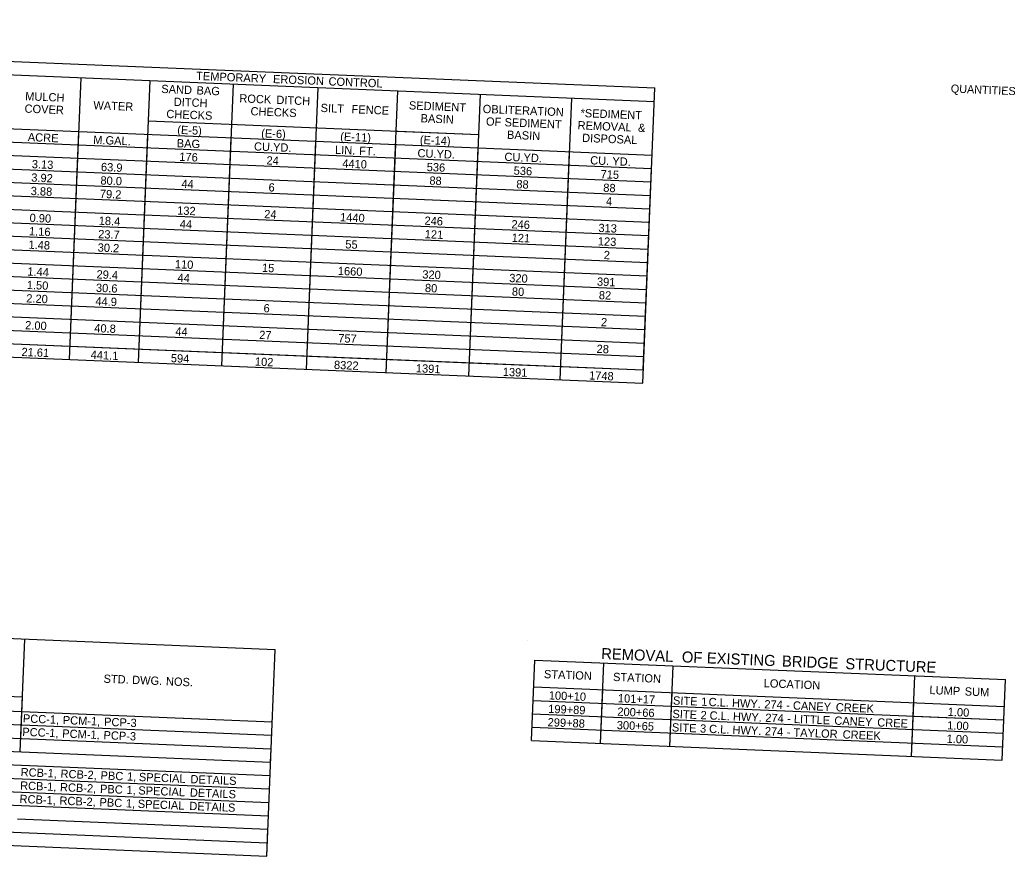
# Model space of a CAD drawing. Extents: x 1164179 to 1171425, y 1655958 to 1657208.
# Drawn here: x 1166854 to 1167576, y 1656540 to 1657146 of the extents above; entities that cross this region are included whole.
import ezdxf

# ---------------------------------------------------------------- set-up
doc = ezdxf.new("R2010")
doc.units = 0
doc.layers.add('Default', color=7, linetype='Continuous')
doc.layers.add('R_Grid', color=7, linetype='Continuous')

msp = doc.modelspace()

# ---------------------------------------------------------------- linework, layer by layer
at = {"layer": 'Default'}
for p, q in [((1166119.48, 1657146.43), (1167314.3, 1657097.01)), ((1166520.92, 1657120.07), (1167313.89, 1657087.27)), ((1166889.46, 1656899.9), (1166897.92, 1657104.47)), ((1166939.63, 1656897.82), (1166948.09, 1657102.4)), ((1167000.03, 1656895.32), (1167008.49, 1657099.9)), ((1167061.4, 1656892.79), (1167069.86, 1657097.36)), ((1167305.43, 1656882.69), (1167314.3, 1657097.01)), ((1167119.36, 1656890.39), (1167127.83, 1657094.96)), ((1167179.28, 1656887.91), (1167187.74, 1657092.48)), ((1167245.52, 1656885.17), (1167253.98, 1657089.74)), ((1166117.06, 1657087.98), (1167311.88, 1657038.56)), ((1166116.66, 1657078.24), (1167311.47, 1657028.82)), ((1166519.31, 1657081.1), (1167186.13, 1657053.52)), ((1166116.26, 1657068.5), (1167311.07, 1657019.07)), ((1166946.88, 1657073.17), (1167186.53, 1657063.26)), ((1166889.46, 1656899.9), (1166896.31, 1657065.51)), ((1166939.63, 1656897.82), (1166946.48, 1657063.43)), ((1167000.03, 1656895.32), (1167006.88, 1657060.93)), ((1167126.62, 1657065.74), (1167186.53, 1657063.26)), ((1166115.85, 1657058.76), (1167310.67, 1657009.33)), ((1167061.4, 1656892.79), (1167068.25, 1657058.39)), ((1167119.36, 1656890.39), (1167126.21, 1657056)), ((1167179.28, 1656887.91), (1167186.13, 1657053.52)), ((1167186.13, 1657053.52), (1167312.28, 1657048.3)), ((1166115.45, 1657049.02), (1167310.27, 1656999.59)), ((1167245.52, 1656885.17), (1167252.37, 1657050.78)), ((1166115.05, 1657039.28), (1167309.86, 1656989.85)), ((1167305.83, 1656892.43), (1167311.88, 1657038.56)), ((1166114.64, 1657029.53), (1167309.46, 1656980.11)), ((1166114.24, 1657019.79), (1167309.06, 1656970.37)), ((1166113.84, 1657010.05), (1167308.65, 1656960.62)), ((1166113.44, 1657000.31), (1167308.25, 1656950.88)), ((1166113.03, 1656990.57), (1167307.85, 1656941.14)), ((1166112.63, 1656980.83), (1167307.44, 1656931.4)), ((1166112.23, 1656971.08), (1167307.04, 1656921.66)), ((1166111.82, 1656961.34), (1167306.64, 1656911.92)), ((1166111.42, 1656951.6), (1167306.24, 1656902.17)), ((1166111.02, 1656941.86), (1167179.68, 1656897.65)), ((1166111.02, 1656941.86), (1167305.83, 1656892.43)), ((1166110.61, 1656932.12), (1167305.43, 1656882.69)), ((1167179.68, 1656897.65), (1167245.92, 1656894.91)), ((1167245.92, 1656894.91), (1167305.83, 1656892.43)), ((1166102.18, 1656728.34), (1167038.85, 1656689.59)), ((1166853.78, 1656615.27), (1166857.16, 1656697.1)), ((1167221.85, 1656695.68), (1167221.85, 1656695.68)), ((1167032.64, 1656539.57), (1167038.85, 1656689.59)), ((1167224.72, 1656623.35), (1167227.13, 1656681.8)), ((1167224.72, 1656623.35), (1167227.13, 1656681.8)), ((1167227.13, 1656681.8), (1167568.58, 1656667.67)), ((1167274.89, 1656621.27), (1167277.3, 1656679.72)), ((1167325.06, 1656619.2), (1167327.47, 1656677.65)), ((1166100.01, 1656675.73), (1167036.67, 1656636.98)), ((1166368.35, 1656675.36), (1166855.43, 1656655.21)), ((1167500.41, 1656611.94), (1167502.82, 1656670.39)), ((1166099.6, 1656665.99), (1167036.27, 1656627.24)), ((1167566.16, 1656609.22), (1167568.58, 1656667.67)), ((1167566.16, 1656609.22), (1167568.58, 1656667.67)), ((1166099.2, 1656656.25), (1167035.86, 1656617.5)), ((1166099.2, 1656656.25), (1167035.86, 1656617.5)), ((1167226.33, 1656662.32), (1167567.77, 1656648.19)), ((1167274.89, 1656621.27), (1167276.5, 1656660.24)), ((1167325.06, 1656619.2), (1167326.67, 1656658.16)), ((1166854.18, 1656625.02), (1166855.43, 1656655.21)), ((1167225.92, 1656652.57), (1167567.37, 1656638.45)), ((1167500.41, 1656611.94), (1167502.02, 1656650.91)), ((1166098.8, 1656646.51), (1167035.46, 1656607.76)), ((1166854.99, 1656644.5), (1167036.67, 1656636.98)), ((1167225.52, 1656642.83), (1167566.97, 1656628.71)), ((1166098.4, 1656636.76), (1167035.06, 1656598.02)), ((1167501.61, 1656641.17), (1167567.37, 1656638.45)), ((1166097.99, 1656627.02), (1167034.65, 1656588.27)), ((1167225.12, 1656633.09), (1167566.56, 1656618.97)), ((1167224.72, 1656623.35), (1167566.16, 1656609.22)), ((1166097.59, 1656617.28), (1167034.25, 1656578.53)), ((1167035.46, 1656607.76), (1167035.86, 1656617.5)), ((1166097.19, 1656607.54), (1167033.85, 1656568.79)), ((1166096.38, 1656588.06), (1167033.04, 1656549.31)), ((1166095.98, 1656578.31), (1167032.64, 1656539.57)), ((1166851.76, 1656566.57), (1167033.45, 1656559.05)), ((1167032.64, 1656539.57), (1167033.45, 1656559.05))]:
    msp.add_line(p, q, dxfattribs=at)

# ---------------------------------------------------------------- texts
for s, height, p in [('TEMPORARY', 6, (1166981.31, 1657102.9)), (' EROSION', 6, (1167034.85, 1657100.69)), (' CONTROL', 6, (1167075.14, 1657099.02)), ('SAND', 6, (1166956.06, 1657093.44)), (' BAG', 6, (1166979.38, 1657092.47)), ('MULCH', 6, (1166857.29, 1657088.14)), ('DITCH', 6, (1166965.09, 1657084.05)), ('ROCK', 6, (1167012.67, 1657086.59)), (' DITCH', 6, (1167037.32, 1657085.57)), ('COVER', 6, (1166856.85, 1657079.15)), ('WATER', 6, (1166906.74, 1657081.59)), ('CHECKS', 6, (1167020.78, 1657077.25)), ('SILT', 6, (1167071.65, 1657079.65)), ('  FENCE', 6, (1167089.63, 1657078.9)), ('SEDIMENT', 6, (1167135.68, 1657081.5)), ('OBLITERATION', 6, (1167189.23, 1657078.91)), ('*SEDIMENT', 6, (1167260.19, 1657075.98)), ('CHECKS', 6, (1166959.71, 1657075.27)), ('BASIN', 6, (1167144.17, 1657072.14)), ('OF', 6, (1167191.59, 1657069.81)), (' SEDIMENT', 6, (1167202.83, 1657069.34)), ('(E-5)', 6, (1166967.64, 1657063.76)), ('(E-6)', 6, (1167028.53, 1657061.24)), ('REMOVAL', 6, (1167258.07, 1657067.06)), (' &', 6, (1167299.71, 1657065.33)), ('ACRE', 6, (1166859.21, 1657058.48)), ('M.GAL.', 6, (1166906.67, 1657056.52)), ('(E-11)', 6, (1167085.87, 1657058.87)), ('(E-14)', 6, (1167143.64, 1657056.48)), ('BASIN', 6, (1167206.86, 1657060.17)), ('DISPOSAL', 6, (1167261.35, 1657057.91)), ('BAG', 6, (1166967.27, 1657054.01)), ('CU.YD.', 6, (1167023.31, 1657051.7)), ('LIN.', 6, (1167082.1, 1657049.26)), (' FT.', 6, (1167097.35, 1657048.63)), ('CU.YD.', 6, (1167141.91, 1657046.79)), ('176', 6, (1166969.13, 1657044.18)), ('24', 6, (1167032.36, 1657041.56)), ('CU.YD.', 6, (1167204.99, 1657044.18)), ('CU.', 6, (1167267.19, 1657041.61)), (' YD.', 6, (1167281.04, 1657041.03)), ('3.13', 6, (1166862.11, 1657038.85)), ('63.9', 6, (1166912.27, 1657036.77)), ('4410', 6, (1167087.37, 1657039.29)), ('536', 6, (1167148.62, 1657036.75)), ('536', 6, (1167211.7, 1657034.14)), ('3.92', 6, (1166861.74, 1657029.1)), ('80.0', 6, (1166911.89, 1657027.03)), ('88', 6, (1167150.54, 1657026.92)), ('715', 6, (1167274.75, 1657031.54)), ('3.88', 6, (1166861.3, 1657019.36)), ('44', 6, (1166970.66, 1657024.6)), ('6', 6, (1167033.86, 1657021.98)), ('88', 6, (1167213.62, 1657024.31)), ('88', 6, (1167276.69, 1657021.7)), ('79.2', 6, (1166911.51, 1657017.29)), ('4', 6, (1167278.64, 1657011.86)), ('132', 6, (1166967.55, 1657005.21)), ('0.90', 6, (1166860.51, 1656999.88)), ('18.4', 6, (1166910.68, 1656997.8)), ('24', 6, (1167030.74, 1657002.6)), ('1440', 6, (1167085.75, 1657000.32)), ('246', 6, (1167147.01, 1656997.79)), ('1.16', 6, (1166860.09, 1656990.14)), ('44', 6, (1166969.46, 1656995.37)), ('246', 6, (1167210.08, 1656995.18)), ('313', 6, (1167273.16, 1656992.57)), ('23.7', 6, (1166910.26, 1656988.06)), ('121', 6, (1167147.18, 1656988.02)), ('121', 6, (1167210.26, 1656985.41)), ('123', 6, (1167272.76, 1656982.83)), ('1.48', 6, (1166859.69, 1656980.4)), ('30.2', 6, (1166909.89, 1656978.32)), ('55', 6, (1167089.57, 1656980.65)), ('2', 6, (1167277.04, 1656972.89)), ('1.44', 6, (1166858.9, 1656960.91)), ('110', 6, (1166965.92, 1656966.24)), ('15', 6, (1167029.1, 1656963.63)), ('1660', 6, (1167084.14, 1656961.35)), ('29.4', 6, (1166909.07, 1656958.84)), ('44', 6, (1166967.84, 1656956.41)), ('320', 6, (1167145.41, 1656958.82)), ('320', 6, (1167208.48, 1656956.21)), ('391', 6, (1167272.13, 1656953.58)), ('1.50', 6, (1166858.49, 1656951.17)), ('30.6', 6, (1166908.65, 1656949.1)), ('80', 6, (1167147.33, 1656948.98)), ('80', 6, (1167210.41, 1656946.37)), ('2.20', 6, (1166858.09, 1656941.43)), ('44.9', 6, (1166908.24, 1656939.36)), ('82', 6, (1167273.51, 1656943.76)), ('6', 6, (1167030.24, 1656934.31)), ('2', 6, (1167275.03, 1656924.18)), ('2.00', 6, (1166857.29, 1656921.95)), ('40.8', 6, (1166907.44, 1656919.87)), ('44', 6, (1166966.23, 1656917.44)), ('27', 6, (1167027.1, 1656914.92)), ('757', 6, (1167084.44, 1656912.55)), ('21.61', 6, (1166854.63, 1656902.54)), ('28', 6, (1167271.86, 1656904.8)), ('441.1', 6, (1166904.8, 1656900.46)), ('594', 6, (1166962.99, 1656898.06)), ('102', 6, (1167023.99, 1656895.53)), ('8322', 6, (1167081.33, 1656893.16)), ('1391', 6, (1167140.74, 1656890.7)), ('1391', 6, (1167203.81, 1656888.1)), ('1748', 6, (1167266.4, 1656885.51)), ('REMOVAL', 8, (1167275.19, 1656682.64)), (' OF', 8, (1167330.7, 1656680.34)), (' EXISTING', 8, (1167348.79, 1656679.59)), (' BRIDGE', 8, (1167403.35, 1656677.34)), (' STRUCTURE', 8, (1167449.34, 1656675.43)), ('STD.', 6, (1166914.15, 1656665.4)), (' DWG.', 6, (1166932.66, 1656664.63)), ('STATION', 6, (1167233.65, 1656668.77)), ('STATION', 6, (1167283.82, 1656666.69)), (' NOS.', 6, (1166957.2, 1656663.61)), ('LOCATION', 6, (1167393.09, 1656662.17)), ('LUMP', 6, (1167513.33, 1656657.2)), ('100+10', 6, (1167237.18, 1656653.31)), ('101+17', 6, (1167287.33, 1656651.23)), (' SUM', 6, (1167536.68, 1656656.23)), ('199+89', 6, (1167236.76, 1656643.57)), ('SITE', 6, (1167327.29, 1656649.58)), (' 1', 6, (1167345.46, 1656648.83)), (' C.L.', 6, (1167350.9, 1656648.6)), (' HWY.', 6, (1167367.85, 1656647.9)), (' 274', 6, (1167391.32, 1656646.93)), (' -', 6, (1167407.2, 1656646.28)), (' CANEY', 6, (1167412.06, 1656646.07)), (' CREEK', 6, (1167443.18, 1656644.79)), ('PCC-1,', 6, (1166855.64, 1656636.59)), (' PCM-1,', 6, (1166882.35, 1656635.48)), ('200+66', 6, (1167286.93, 1656641.49)), ('SITE', 6, (1167326.88, 1656639.84)), (' 2', 6, (1167345.06, 1656639.09)), (' C.L.', 6, (1167351.6, 1656638.82)), (' HWY.', 6, (1167368.55, 1656638.12)), (' 274', 6, (1167392.01, 1656637.15)), (' LITTLE', 6, (1167412.75, 1656636.29)), ('1.00', 6, (1167526.6, 1656641.34)), (' PCP-3', 6, (1166912.31, 1656634.25)), ('299+88', 6, (1167236.35, 1656633.83)), ('300+65', 6, (1167286.5, 1656631.75)), ('SITE', 6, (1167326.48, 1656630.1)), (' 3', 6, (1167344.65, 1656629.35)), (' C.L.', 6, (1167351.26, 1656629.07)), (' HWY.', 6, (1167368.21, 1656628.37)), (' -', 6, (1167407.9, 1656636.49)), (' CANEY', 6, (1167442.09, 1656635.07)), (' CREE', 6, (1167473.22, 1656633.79)), ('1.00', 6, (1167526.19, 1656631.59)), ('PCC-1,', 6, (1166855.23, 1656626.85)), (' PCM-1,', 6, (1166881.94, 1656625.74)), (' PCP-3', 6, (1166911.91, 1656624.5)), (' 274', 6, (1167391.67, 1656627.4)), (' -', 6, (1167407.56, 1656626.74)), (' TAYLOR', 6, (1167412.41, 1656626.54)), (' CREEK', 6, (1167448.14, 1656625.07)), ('1.00', 6, (1167525.79, 1656621.85)), ('RCB-1,', 6, (1166854.02, 1656597.62)), (' RCB-2,', 6, (1166880.74, 1656596.52)), (' PBC', 6, (1166909.77, 1656595.32)), (' 1,', 6, (1166928.99, 1656594.52)), (' SPECIAL', 6, (1166937.55, 1656594.17)), (' DETAILS', 6, (1166974.97, 1656592.62)), ('RCB-1,', 6, (1166853.62, 1656587.88)), (' RCB-2,', 6, (1166880.33, 1656586.78)), (' PBC', 6, (1166909.37, 1656585.58)), ('RCB-1,', 6, (1166853.22, 1656578.14)), (' 1,', 6, (1166928.59, 1656584.78)), (' SPECIAL', 6, (1166937.15, 1656584.43)), (' DETAILS', 6, (1166974.56, 1656582.88)), (' RCB-2,', 6, (1166879.93, 1656577.03)), (' PBC', 6, (1166908.97, 1656575.83)), (' 1,', 6, (1166928.19, 1656575.04)), (' SPECIAL', 6, (1166936.75, 1656574.68)), (' DETAILS', 6, (1166974.16, 1656573.14))]:
    msp.add_text(s, height=height, rotation=357.63112, dxfattribs=at).set_placement(p)
at = {"layer": 'R_Grid'}
msp.add_text('QUANTITIES', height=5.862, rotation=357.63112, dxfattribs=at).set_placement((1167528.85, 1657093.75))

doc.saveas('drawing.dxf')
